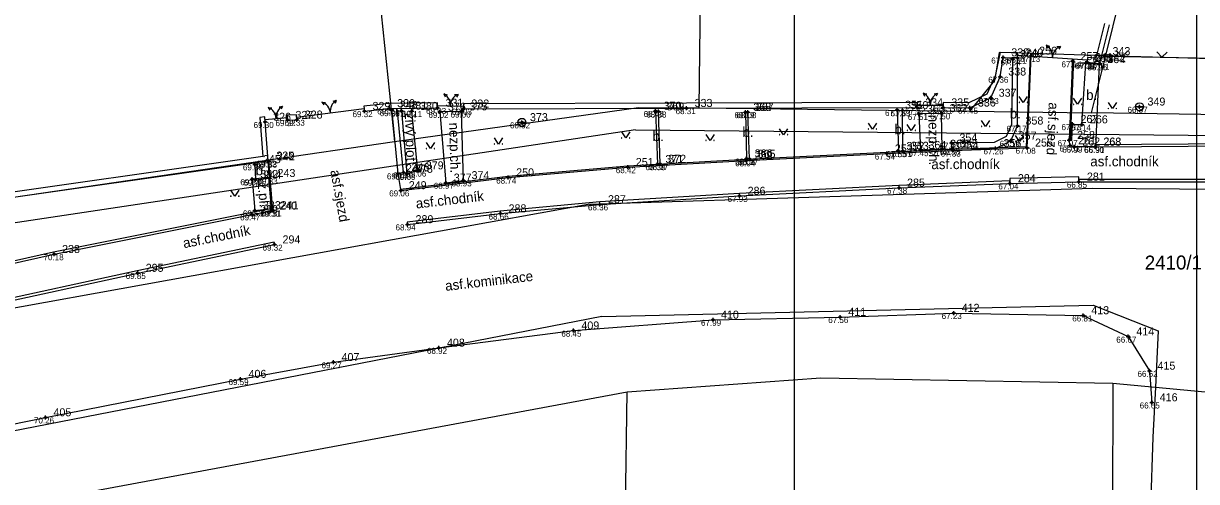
# Model space of a CAD drawing. Extents: x -454285 to -453563, y -1108687 to -1108249.
# Drawn here: x -453927.9 to -453869.2, y -1108486.5 to -1108463.6 of the extents above; entities that cross this region are included whole.
import ezdxf

# ---------------------------------------------------------------- set-up
doc = ezdxf.new("R2010")
doc.units = 0
for name, color, linetype in [('1', 7, 'Continuous'), ('16', 7, 'Continuous'), ('2', 7, 'Continuous'), ('beton', 7, 'Continuous'), ('BODY_T1_2018', 7, 'Continuous'), ('CISLA_T1_2018', 7, 'Continuous'), ('nezp.chodník', 7, 'Continuous'), ('obrubník', 7, 'Continuous'), ('okraj asf.komunikace', 7, 'Continuous'), ('oplocení', 7, 'Continuous'), ('rozhraní', 7, 'Continuous'), ('rámy', 7, 'Continuous'), ('sloup', 7, 'Continuous'), ('T', 7, 'Continuous'), ('VYSKY_T1_2018', 7, 'Continuous'), ('zeleň', 7, 'Continuous'), ('živý plot', 7, 'Continuous')]:
    doc.layers.add(name, color=color, linetype=linetype)

# ---------------------------------------------------------------- blocks, each defined once
blk = doc.blocks.new('EL.SLOUP')
blk.add_line((0.4, 0), (-0.4, 0))
blk.add_line((0.4, 0), (-0.4, 0))
blk.add_lwpolyline([(0.4, 0), (-0.4, 0)])
blk.add_lwpolyline([(0.4, 0), (-0.4, 0)])
blk.add_circle((0, 0), 0.4)
blk.add_circle((0, 0), 0.4)
for start, end in [(270, 0), (270, 0), (180, 270), (180, 270)]:
    blk.add_arc((0, 0), 0.4, start, end)
blk = doc.blocks.new('PARK')
for p, q in [((0, 0), (-1, 1.5)), ((1, 1.5), (0, 0))]:
    blk.add_line(p, q)
for centre, start, end in [((-1, 0), 0, 180), ((1, 0), 0, 180), ((1, 0), 180, 0), ((-1, 0), 180, 0)]:
    blk.add_arc(centre, 0.05, start, end)
blk = doc.blocks.new('BRANKA')
for p, q in [((-0.351, 0.589), (-0.179, 0.552)), ((-0.351, 0.589), (-0.284, 0.449)), ((0.361, 0.583), (0.188, 0.549)), ((0.361, 0.583), (0.291, 0.445))]:
    blk.add_line(p, q)
for centre, start, end in [((-0.618, 0.03), 357.17506, 64.46884), ((0.619, 0.02), 114.58945, 181.88322)]:
    blk.add_arc(centre, 0.619, start, end)
blk = doc.blocks.new('PLOT05')
for q in [(-0.265, 0.265), (0.265, 0.265)]:
    blk.add_line((0, 0), q)
blk = doc.blocks.new('POINT_DISPLAY')
for p, q in [((-0.1, 0), (0.1, 0)), ((0, -0.1), (0, 0.1))]:
    blk.add_line(p, q)
blk.add_circle((0, 0), 0.05)
blk = doc.blocks.new('t1_2018')
at = {"layer": 'BODY_T1_2018'}
for p in [(-453878.87, -1108465.26), (-453878.41, -1108465.35), (-453878.16, -1108465.27), (-453877.48, -1108465.18), (-453873.81, -1108465.2), (-453875.41, -1108465.45), (-453874.74, -1108465.54), (-453874.68, -1108465.5), (-453874.07, -1108465.6), (-453874.04, -1108465.56), (-453879.02, -1108466.22), (-453879.5, -1108467.28), (-453910.8, -1108467.94), (-453909.57, -1108467.8), (-453909.44, -1108467.89), (-453908.96, -1108467.92), (-453908.43, -1108467.94), (-453907.15, -1108467.78), (-453907.03, -1108467.98), (-453905.95, -1108467.96), (-453905.86, -1108467.82), (-453896.25, -1108467.93), (-453896.11, -1108467.96), (-453894.7, -1108467.79), (-453891.76, -1108467.99), (-453891.64, -1108467.99), (-453884.18, -1108467.88), (-453883.91, -1108467.9), (-453883.17, -1108467.76), (-453883.09, -1108468.08), (-453881.95, -1108468.05), (-453881.87, -1108467.76), (-453880.54, -1108467.77), (-453872.06, -1108467.72), (-453915.77, -1108468.48), (-453914.65, -1108468.39), (-453914.19, -1108468.37), (-453902.93, -1108468.5), (-453878.16, -1108468.67), (-453875.41, -1108468.59), (-453874.94, -1108468.61), (-453878.5, -1108469.42), (-453875.58, -1108469.39), (-453884.11, -1108469.94), (-453883.89, -1108469.93), (-453883.01, -1108469.89), (-453881.93, -1108469.83), (-453881.46, -1108469.52), (-453881.44, -1108469.82), (-453881.4, -1108469.91), (-453879.26, -1108469.8), (-453877.68, -1108469.77), (-453875.53, -1108469.66), (-453875.32, -1108469.72), (-453874.27, -1108469.73), (-453874.26, -1108469.72), (-453916.28, -1108470.6), (-453915.61, -1108470.42), (-453915.58, -1108470.46), (-453896.16, -1108470.59), (-453896.02, -1108470.58), (-453891.7, -1108470.31), (-453891.7, -1108470.4), (-453891.55, -1108470.33), (-453884.69, -1108470.06), (-453909.13, -1108471.05), (-453908.85, -1108471), (-453908.68, -1108471.08), (-453908.14, -1108470.91), (-453897.64, -1108470.74), (-453916.41, -1108471.34), (-453916.25, -1108471.37), (-453915.55, -1108471.29), (-453906.74, -1108471.52), (-453905.85, -1108471.4), (-453903.62, -1108471.26), (-453884.08, -1108471.77), (-453878.54, -1108471.55), (-453875.09, -1108471.47), (-453908.99, -1108471.9), (-453892.05, -1108472.18), (-453916.28, -1108472.9), (-453915.46, -1108472.92), (-453915.39, -1108472.9), (-453899.03, -1108472.6), (-453916.42, -1108473.1), (-453904, -1108473.06), (-453908.65, -1108473.6), (-453915.3, -1108474.61), (-453926.32, -1108475.09), (-453922.14, -1108476.03), (-453887.02, -1108478.23), (-453881.35, -1108478.03), (-453874.87, -1108478.15), (-453893.38, -1108478.37), (-453900.36, -1108478.91), (-453872.62, -1108479.21), (-453907.08, -1108479.77), (-453912.35, -1108480.49), (-453871.56, -1108480.92), (-453917, -1108481.33), (-453871.45, -1108482.5), (-453926.75, -1108483.25)]:
    blk.add_blockref('POINT_DISPLAY', p, dxfattribs=at)
at = {"layer": 'CISLA_T1_2018'}
for s, p in [('339', (-453878.47, -1108465.2)), ('360', (-453878.01, -1108465.29)), ('340', (-453877.76, -1108465.21)), ('256', (-453877.08, -1108465.12)), ('257', (-453875.01, -1108465.39)), ('265', (-453874.34, -1108465.48)), ('341', (-453874.28, -1108465.44)), ('264', (-453873.67, -1108465.54)), ('342', (-453873.64, -1108465.5)), ('343', (-453873.41, -1108465.14)), ('338', (-453878.62, -1108466.16)), ('337', (-453879.1, -1108467.22)), ('329', (-453910.4, -1108467.88)), ('330', (-453909.17, -1108467.74)), ('248', (-453909.04, -1108467.83)), ('381', (-453908.56, -1108467.86)), ('380', (-453908.03, -1108467.88)), ('331', (-453906.75, -1108467.72)), ('376', (-453906.63, -1108467.92)), ('375', (-453905.55, -1108467.9)), ('332', (-453905.46, -1108467.76)), ('370', (-453895.85, -1108467.87)), ('369', (-453895.71, -1108467.9)), ('333', (-453894.3, -1108467.73)), ('368', (-453891.36, -1108467.93)), ('367', (-453891.24, -1108467.93)), ('351', (-453883.78, -1108467.82)), ('350', (-453883.51, -1108467.84)), ('334', (-453882.77, -1108467.7)), ('362', (-453881.55, -1108467.99)), ('335', (-453881.47, -1108467.7)), ('336', (-453880.14, -1108467.71)), ('349', (-453871.66, -1108467.66)), ('326', (-453915.37, -1108468.42)), ('327', (-453914.25, -1108468.33)), ('328', (-453913.79, -1108468.31)), ('373', (-453902.53, -1108468.44)), ('363', (-453882.69, -1108468.02)), ('267', (-453875.01, -1108468.53)), ('266', (-453874.54, -1108468.55)), ('358', (-453877.76, -1108468.61)), ('354', (-453881.06, -1108469.46)), ('355', (-453881.04, -1108469.76)), ('356', (-453878.86, -1108469.74)), ('357', (-453878.1, -1108469.36)), ('255', (-453877.28, -1108469.71)), ('258', (-453875.18, -1108469.33)), ('261', (-453875.13, -1108469.6)), ('262', (-453874.92, -1108469.66)), ('268', (-453873.87, -1108469.67)), ('263', (-453873.86, -1108469.66)), ('366', (-453891.3, -1108470.25)), ('252', (-453891.3, -1108470.34)), ('365', (-453891.15, -1108470.27)), ('253', (-453884.29, -1108470)), ('352', (-453883.71, -1108469.88)), ('353', (-453883.49, -1108469.87)), ('364', (-453882.61, -1108469.83)), ('361', (-453881.53, -1108469.77)), ('254', (-453881, -1108469.85)), ('245', (-453915.88, -1108470.54)), ('325', (-453915.21, -1108470.36)), ('242', (-453915.18, -1108470.4)), ('379', (-453907.74, -1108470.85)), ('251', (-453897.24, -1108470.68)), ('371', (-453895.76, -1108470.53)), ('372', (-453895.62, -1108470.52)), ('382', (-453916.01, -1108471.28)), ('244', (-453915.85, -1108471.31)), ('243', (-453915.15, -1108471.23)), ('247', (-453908.73, -1108470.99)), ('246', (-453908.45, -1108470.94)), ('378', (-453908.28, -1108471.02)), ('377', (-453906.34, -1108471.46)), ('374', (-453905.45, -1108471.34)), ('250', (-453903.22, -1108471.2)), ('284', (-453878.14, -1108471.49)), ('281', (-453874.69, -1108471.41)), ('249', (-453908.59, -1108471.84)), ('285', (-453883.68, -1108471.71)), ('287', (-453898.63, -1108472.54)), ('286', (-453891.65, -1108472.12)), ('239', (-453916.02, -1108473.04)), ('383', (-453915.88, -1108472.84)), ('240', (-453915.06, -1108472.86)), ('241', (-453914.99, -1108472.84)), ('288', (-453903.6, -1108473)), ('289', (-453908.25, -1108473.54)), ('238', (-453925.92, -1108475.03)), ('294', (-453914.9, -1108474.55)), ('295', (-453921.74, -1108475.97)), ('412', (-453880.95, -1108477.97)), ('410', (-453892.98, -1108478.31)), ('411', (-453886.62, -1108478.17)), ('413', (-453874.47, -1108478.09)), ('409', (-453899.96, -1108478.85)), ('408', (-453906.68, -1108479.71)), ('414', (-453872.22, -1108479.15)), ('407', (-453911.95, -1108480.43)), ('415', (-453871.16, -1108480.86)), ('406', (-453916.6, -1108481.27)), ('416', (-453871.05, -1108482.44)), ('405', (-453926.35, -1108483.19))]:
    blk.add_text(s, height=0.4, dxfattribs=at).set_placement(p)
at = {"layer": 'VYSKY_T1_2018'}
for s, p in [('67.13', (-453878.03, -1108465.48)), ('66.99', (-453874.41, -1108465.5)), ('67.36', (-453879.47, -1108465.56)), ('67.34', (-453879.01, -1108465.65)), ('67.21', (-453878.71, -1108465.57)), ('67.14', (-453875.96, -1108465.75)), ('67.18', (-453875.29, -1108465.84)), ('67.17', (-453875.23, -1108465.8)), ('66.96', (-453874.67, -1108465.9)), ('67.01', (-453874.565, -1108465.86)), ('67.36', (-453879.62, -1108466.52)), ('67.43', (-453880.1, -1108467.58)), ('69.32', (-453911.4, -1108468.24)), ('69.29', (-453910.17, -1108468.1)), ('69.28', (-453910.04, -1108468.19)), ('69.10', (-453909.485, -1108468.22)), ('69.11', (-453908.93, -1108468.24)), ('69.03', (-453907.725, -1108468.08)), ('69.02', (-453907.605, -1108468.28)), ('69.00', (-453906.5, -1108468.26)), ('69.03', (-453906.435, -1108468.12)), ('68.48', (-453896.85, -1108468.23)), ('68.38', (-453896.71, -1108468.26)), ('68.31', (-453895.25, -1108468.09)), ('68.19', (-453892.31, -1108468.29)), ('68.08', (-453892.215, -1108468.29)), ('67.73', (-453884.78, -1108468.18)), ('67.53', (-453884.51, -1108468.2)), ('67.52', (-453883.77, -1108468.06)), ('67.51', (-453883.64, -1108468.38)), ('67.50', (-453882.525, -1108468.35)), ('67.51', (-453882.42, -1108468.06)), ('67.45', (-453881.14, -1108468.07)), ('66.87', (-453872.66, -1108468.02)), ('69.30', (-453916.345, -1108468.78)), ('69.32', (-453915.25, -1108468.69)), ('69.33', (-453914.79, -1108468.67)), ('68.82', (-453903.53, -1108468.8)), ('67.17', (-453878.71, -1108468.97)), ('67.13', (-453875.96, -1108468.89)), ('67.14', (-453875.49, -1108468.91)), ('67.55', (-453884.71, -1108470.24)), ('67.51', (-453884.44, -1108470.23)), ('67.45', (-453883.61, -1108470.19)), ('67.41', (-453882.48, -1108470.13)), ('67.43', (-453882.06, -1108469.82)), ('67.38', (-453882.04, -1108470.12)), ('67.33', (-453882, -1108470.21)), ('67.26', (-453879.86, -1108470.1)), ('67.19', (-453879.05, -1108469.72)), ('67.08', (-453878.255, -1108470.07)), ('67.07', (-453876.155, -1108469.69)), ('67.01', (-453876.055, -1108469.96)), ('66.99', (-453875.92, -1108470.02)), ('66.90', (-453874.835, -1108470.02)), ('66.91', (-453874.82, -1108470.03)), ('69.32', (-453916.21, -1108470.72)), ('69.33', (-453916.18, -1108470.76)), ('68.08', (-453892.275, -1108470.61)), ('68.04', (-453892.275, -1108470.7)), ('68.07', (-453892.125, -1108470.63)), ('67.54', (-453885.29, -1108470.36)), ('69.85', (-453916.88, -1108470.9)), ('69.14', (-453909.68, -1108471.35)), ('69.10', (-453909.375, -1108471.3)), ('69.09', (-453909.255, -1108471.38)), ('69.06', (-453908.715, -1108471.21)), ('68.42', (-453898.24, -1108471.04)), ('68.38', (-453896.76, -1108470.89)), ('68.37', (-453896.62, -1108470.88)), ('69.84', (-453917.01, -1108471.64)), ('69.79', (-453916.85, -1108471.67)), ('69.33', (-453916.15, -1108471.59)), ('68.97', (-453907.34, -1108471.82)), ('68.93', (-453906.45, -1108471.7)), ('68.74', (-453904.22, -1108471.56)), ('67.04', (-453879.115, -1108471.85)), ('66.85', (-453875.69, -1108471.77)), ('69.06', (-453909.565, -1108472.2)), ('67.93', (-453892.65, -1108472.48)), ('67.38', (-453884.68, -1108472.07)), ('68.36', (-453899.63, -1108472.9)), ('69.47', (-453917.02, -1108473.4)), ('69.53', (-453916.88, -1108473.2)), ('69.31', (-453916.01, -1108473.22)), ('69.31', (-453915.94, -1108473.2)), ('68.66', (-453904.6, -1108473.36)), ('68.94', (-453909.25, -1108473.9)), ('69.32', (-453915.9, -1108474.91)), ('70.18', (-453926.845, -1108475.39)), ('69.85', (-453922.74, -1108476.33)), ('67.23', (-453881.95, -1108478.33)), ('66.81', (-453875.42, -1108478.45)), ('67.99', (-453893.98, -1108478.67)), ('67.56', (-453887.62, -1108478.53)), ('68.45', (-453900.96, -1108479.21)), ('66.67', (-453873.22, -1108479.51)), ('68.92', (-453907.68, -1108480.07)), ('69.27', (-453912.95, -1108480.79)), ('66.62', (-453872.16, -1108481.22)), ('69.59', (-453917.6, -1108481.63)), ('66.65', (-453872.05, -1108482.8)), ('70.26', (-453927.325, -1108483.55))]:
    blk.add_text(s, height=0.3, dxfattribs=at).set_placement(p)

msp = doc.modelspace()

# ---------------------------------------------------------------- linework, layer by layer
at = {"layer": '1'}
for p, q in [((-453912.107, -1108442.251), (-453909.307, -1108469.461)), ((-453873.747, -1108465.151), (-453869.597, -1108448.591)), ((-453894.067, -1108467.771), (-453893.947, -1108457.011)), ((-453874.467, -1108468.031), (-453873.747, -1108465.151)), ((-453873.747, -1108465.151), (-453840.987, -1108466.171)), ((-453909.307, -1108469.461), (-453897.107, -1108467.751)), ((-453897.107, -1108467.751), (-453894.067, -1108467.771)), ((-453894.067, -1108467.771), (-453880.537, -1108467.941)), ((-453880.537, -1108467.941), (-453874.467, -1108468.031)), ((-453813.137, -1108468.941), (-453874.467, -1108468.031)), ((-453897.257, -1108468.871), (-453930.727, -1108473.891)), ((-453897.257, -1108468.871), (-453776.927, -1108470.061)), ((-453930.957, -1108472.621), (-453909.307, -1108469.461)), ((-453897.667, -1108481.961), (-453887.987, -1108481.271)), ((-453887.987, -1108481.271), (-453873.387, -1108481.541)), ((-453873.387, -1108481.541), (-453873.447, -1108503.261)), ((-453873.387, -1108481.541), (-453871.267, -1108481.741)), ((-453925.217, -1108487.081), (-453897.667, -1108481.961)), ((-453898.037, -1108505.081), (-453897.667, -1108481.961)), ((-453871.267, -1108481.741), (-453865.837, -1108482.251))]:
    msp.add_line(p, q, dxfattribs=at)
at = {"layer": '2'}
for p, q in [((-453879.317, -1108466.431), (-453879.017, -1108464.991)), ((-453879.017, -1108464.991), (-453873.747, -1108465.151)), ((-453880.067, -1108467.361), (-453879.317, -1108466.431)), ((-453880.537, -1108467.941), (-453880.067, -1108467.361)), ((-453899.627, -1108472.581), (-453874.387, -1108471.791)), ((-453874.387, -1108471.791), (-453858.457, -1108471.891)), ((-453931.507, -1108478.341), (-453899.627, -1108472.581)), ((-453898.937, -1108478.211), (-453874.377, -1108477.631)), ((-453874.377, -1108477.631), (-453871.127, -1108478.921)), ((-453898.937, -1108478.211), (-453931.337, -1108484.501)), ((-453871.127, -1108478.921), (-453871.267, -1108481.741)), ((-453871.267, -1108481.741), (-453871.397, -1108484.241)), ((-453871.397, -1108484.241), (-453873.167, -1108541.891))]:
    msp.add_line(p, q, dxfattribs=at)
at = {"layer": 'beton'}
for points in [[(-453881.44, -1108469.82), (-453879.26, -1108469.8), (-453878.5, -1108469.42), (-453878.16, -1108468.67), (-453878.16, -1108465.27), (-453878.409, -1108465.266), (-453878.458, -1108468.601), (-453878.729, -1108469.199), (-453879.332, -1108469.5), (-453881.46, -1108469.52)], [(-453874.74, -1108465.54), (-453874.07, -1108465.6), (-453874.26, -1108469.72), (-453875.32, -1108469.72), (-453875.53, -1108469.66), (-453875.58, -1108469.39), (-453875.446, -1108469.397), (-453875.41, -1108468.59), (-453874.94, -1108468.61)]]:
    msp.add_lwpolyline(points, close=True, dxfattribs=at)
for points in [[(-453909.449, -1108467.799), (-453909.13, -1108471.05), (-453908.85, -1108471), (-453909.164, -1108467.797)], [(-453896.25, -1108467.93), (-453896.16, -1108470.59), (-453896.02, -1108470.58), (-453896.11, -1108467.96)], [(-453891.76, -1108467.99), (-453891.7, -1108470.31), (-453891.55, -1108470.33), (-453891.64, -1108467.99)], [(-453884.18, -1108467.88), (-453884.11, -1108469.94), (-453883.89, -1108469.93), (-453883.91, -1108467.9)], [(-453916.28, -1108470.6), (-453916.25, -1108471.37), (-453915.55, -1108471.29)]]:
    msp.add_lwpolyline(points, dxfattribs=at)
at = {"layer": 'nezp.chodník'}
for points in [[(-453906.74, -1108471.52), (-453905.85, -1108471.4), (-453905.95, -1108467.96), (-453907.03, -1108467.98)], [(-453883.09, -1108468.08), (-453883.01, -1108469.89), (-453881.93, -1108469.83), (-453881.95, -1108468.05)]]:
    msp.add_lwpolyline(points, close=True, dxfattribs=at)
at = {"layer": 'obrubník'}
for points in [[(-453877.53, -1108465.178), (-453877.728, -1108469.722), (-453881.402, -1108469.86), (-453884.692, -1108470.01), (-453891.703, -1108470.35), (-453897.644, -1108470.69), (-453903.625, -1108471.21), (-453908.996, -1108471.85), (-453908.99, -1108471.9), (-453903.62, -1108471.26), (-453897.64, -1108470.74), (-453891.7, -1108470.4), (-453884.69, -1108470.06), (-453881.4, -1108469.91), (-453877.68, -1108469.77), (-453877.48, -1108465.18)], [(-453875.405, -1108465.327), (-453875.58, -1108469.39)], [(-453875.355, -1108465.33), (-453875.53, -1108469.392)]]:
    msp.add_lwpolyline(points, dxfattribs=at)
for points in [[(-453841.72, -1108466.249), (-453841.72, -1108467.493), (-453841.073, -1108467.473), (-453841.147, -1108469.987), (-453850.248, -1108469.69), (-453860.35, -1108469.53), (-453874.271, -1108469.63), (-453874.27, -1108469.73), (-453860.35, -1108469.63), (-453850.25, -1108469.79), (-453841.05, -1108470.09), (-453840.97, -1108467.37), (-453841.62, -1108467.39), (-453841.62, -1108466.253)], [(-453915.63, -1108470.464), (-453915.44, -1108472.904), (-453915.39, -1108472.9), (-453915.58, -1108470.46)], [(-453908.65, -1108473.6), (-453904, -1108473.06), (-453899.03, -1108472.6), (-453892.05, -1108472.18), (-453884.08, -1108471.77), (-453878.54, -1108471.55), (-453878.544, -1108471.43), (-453884.085, -1108471.65), (-453892.057, -1108472.06), (-453899.039, -1108472.48), (-453904.012, -1108472.941), (-453908.664, -1108473.481)], [(-453875.096, -1108471.22), (-453878.546, -1108471.3), (-453878.54, -1108471.55), (-453875.09, -1108471.47)], [(-453841.256, -1108471.69), (-453847.647, -1108471.49), (-453853.778, -1108471.38), (-453858.819, -1108471.3), (-453866.8, -1108471.35), (-453875.091, -1108471.35), (-453875.09, -1108471.47), (-453866.8, -1108471.47), (-453858.82, -1108471.42), (-453853.78, -1108471.5), (-453847.65, -1108471.61), (-453841.26, -1108471.81)], [(-453915.478, -1108472.822), (-453916.439, -1108473.002), (-453926.341, -1108474.992), (-453936.153, -1108477.193), (-453942.994, -1108478.873), (-453947.721, -1108480.086), (-453948.462, -1108475.972), (-453948.56, -1108475.99), (-453947.8, -1108480.21), (-453942.97, -1108478.97), (-453936.13, -1108477.29), (-453926.32, -1108475.09), (-453916.42, -1108473.1), (-453915.46, -1108472.92)], [(-453947.34, -1108481.91), (-453941.57, -1108480.43), (-453935.77, -1108479.03), (-453929.97, -1108477.73), (-453922.14, -1108476.03), (-453915.3, -1108474.61), (-453915.324, -1108474.493), (-453922.165, -1108475.913), (-453929.996, -1108477.613), (-453935.797, -1108478.913), (-453941.599, -1108480.314), (-453947.37, -1108481.794)]]:
    msp.add_lwpolyline(points, close=True, dxfattribs=at)
at = {"layer": 'okraj asf.komunikace'}
msp.add_lwpolyline([(-453982.81, -1108509.99), (-453983.85, -1108505.12), (-453983.55, -1108502.51), (-453982.48, -1108500.59), (-453972.21, -1108496.2), (-453961.66, -1108492.56), (-453950.2, -1108489.09), (-453937.41, -1108485.39), (-453932.25, -1108484.37), (-453926.75, -1108483.25), (-453917, -1108481.33), (-453912.35, -1108480.49), (-453907.08, -1108479.77), (-453900.36, -1108478.91), (-453893.38, -1108478.37), (-453887.02, -1108478.23), (-453881.35, -1108478.03), (-453874.87, -1108478.15), (-453872.62, -1108479.21), (-453871.56, -1108480.92), (-453871.45, -1108482.5)], dxfattribs=at)
at = {"layer": 'oplocení'}
for p, q in [((-453874.23, -1108465.291), (-453873.798, -1108463.565)), ((-453874.04, -1108465.56), (-453873.555, -1108463.626)), ((-453878.158, -1108465.145), (-453874.668, -1108465.376)), ((-453914.195, -1108468.245), (-453910.814, -1108467.816)), ((-453907.151, -1108467.655), (-453905.86, -1108467.695)), ((-453883.17, -1108467.635), (-453881.87, -1108467.635)), ((-453915.78, -1108468.355), (-453914.655, -1108468.265))]:
    msp.add_line(p, q, dxfattribs=at)
for points in [[(-453878.156, -1108465.02), (-453879.083, -1108465.007), (-453879.262, -1108466.148), (-453879.69, -1108467.093), (-453880.595, -1108467.52), (-453881.869, -1108467.51), (-453881.87, -1108467.76), (-453880.54, -1108467.77), (-453879.5, -1108467.28), (-453879.02, -1108466.22), (-453878.87, -1108465.26), (-453878.16, -1108465.27)], [(-453907.152, -1108467.53), (-453909.585, -1108467.55), (-453910.828, -1108467.692), (-453910.8, -1108467.94), (-453909.57, -1108467.8), (-453907.15, -1108467.78)], [(-453883.17, -1108467.51), (-453894.701, -1108467.54), (-453905.861, -1108467.57), (-453905.86, -1108467.82), (-453894.7, -1108467.79), (-453883.17, -1108467.76)], [(-453914.201, -1108468.12), (-453914.661, -1108468.14), (-453914.65, -1108468.39), (-453914.19, -1108468.37)], [(-453916.04, -1108468.251), (-453915.879, -1108470.206), (-453931.087, -1108472.373), (-453942.169, -1108474.133), (-453947.239, -1108474.943), (-453947.2, -1108475.19), (-453942.13, -1108474.38), (-453931.05, -1108472.62), (-453915.61, -1108470.42), (-453915.77, -1108468.48), (-453915.791, -1108468.231)]]:
    msp.add_lwpolyline(points, close=True, dxfattribs=at)
for points in [[(-453873.81, -1108465.2), (-453866.4, -1108465.33), (-453855.45, -1108465.69), (-453840.96, -1108466.28)], [(-453874.23, -1108465.291), (-453874.657, -1108465.251), (-453874.68, -1108465.5), (-453874.04, -1108465.56)]]:
    msp.add_lwpolyline(points, dxfattribs=at)
at = {"layer": 'rozhraní'}
msp.add_lwpolyline([(-453909.13, -1108471.05), (-453908.996, -1108471.85)], dxfattribs=at)
at = {"layer": 'rámy'}
for points in [[(-453968.38, -1108440.904), (-453869.211, -1108440.904), (-453869.211, -1108500.955), (-453968.38, -1108500.955)], [(-453889.309, -1108441.707), (-453790.141, -1108441.707), (-453790.141, -1108501.759), (-453889.309, -1108501.759)]]:
    msp.add_lwpolyline(points, close=True, dxfattribs=at)
at = {"layer": 'živý plot'}
msp.add_lwpolyline([(-453908.96, -1108467.92), (-453908.68, -1108471.08), (-453908.14, -1108470.91), (-453908.43, -1108467.94)], dxfattribs=at)
msp.add_lwpolyline([(-453916.41, -1108471.34), (-453916.28, -1108472.9), (-453915.458, -1108472.805), (-453915.582, -1108471.252)], close=True, dxfattribs=at)

# ---------------------------------------------------------------- block references
msp.add_blockref('t1_2018', (0, 0))
at = {"layer": 'oplocení'}
for name, p, rotation in [('BRANKA', (-453876.413, -1108465.26), -3.7793052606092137), ('PLOT05', (-453872.941, -1108465.215), -1.0050860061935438), ('PLOT05', (-453870.941, -1108465.25), -1.0050860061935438), ('BRANKA', (-453912.505, -1108468.03), 7.236012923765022), ('BRANKA', (-453906.506, -1108467.675), -1.7749164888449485), ('BRANKA', (-453915.218, -1108468.31), 4.589985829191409)]:
    msp.add_blockref(name, p, dxfattribs=dict(at, rotation=rotation))
msp.add_blockref('BRANKA', (-453882.52, -1108467.635), dxfattribs=at)
at = {"layer": 'sloup', "xscale": 0.5, "yscale": 0.5}
for p in [(-453872.06, -1108467.72), (-453902.93, -1108468.5)]:
    msp.add_blockref('EL.SLOUP', p, dxfattribs=at)
at = {"layer": 'zeleň', "xscale": 0.2, "yscale": 0.20000000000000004}
for p in [(-453877.874, -1108467.503), (-453875.156, -1108467.596), (-453873.415, -1108467.807), (-453885.411, -1108468.838), (-453883.469, -1108468.903), (-453879.751, -1108468.703), (-453904.109, -1108469.582), (-453897.745, -1108469.281), (-453893.526, -1108469.403), (-453889.849, -1108469.121), (-453878.053, -1108469.454), (-453907.507, -1108469.812), (-453917.285, -1108472.188)]:
    msp.add_blockref('PARK', p, dxfattribs=at)

# ---------------------------------------------------------------- texts
at = {"layer": '16'}
msp.add_text('2410/1', height=0.7, rotation=0.1968, dxfattribs=at).set_placement((-453871.797, -1108475.861))
at = {"layer": 'T'}
for s, p in [('b.', (-453874.729, -1108467.38)), ('b.', (-453878.549, -1108468.306)), ('b.', (-453891.911, -1108469.229)), ('b.', (-453884.31, -1108469.098)), ('b.', (-453896.401, -1108469.438)), ('asf.chodník', (-453882.467, -1108470.838)), ('asf.chodník', (-453874.521, -1108470.699)), ('b.', (-453916.247, -1108471.146))]:
    msp.add_text(s, height=0.5, dxfattribs=at).set_placement(p)
for s, rotation, p in [('asf.sjezd', 267.50503, (-453876.596, -1108467.493)), ('živý plot', 271.66511, (-453908.785, -1108468.034)), ('nezp.ch.', 270.64375, (-453882.612, -1108468.121)), ('nezp.ch.', 271.66511, (-453906.575, -1108468.517)), ('asf.sjezd', 280.20923, (-453912.512, -1108470.919)), ('ž.pl.', 274.76364, (-453916.143, -1108471.531)), ('asf.chodník', 6.62403, (-453908.21, -1108472.81)), ('asf.chodník', 11.36557, (-453919.825, -1108474.793)), ('asf.kominikace', 6.62403, (-453906.744, -1108476.926))]:
    msp.add_text(s, height=0.5, rotation=rotation, dxfattribs=at).set_placement(p)

doc.saveas('drawing.dxf')
